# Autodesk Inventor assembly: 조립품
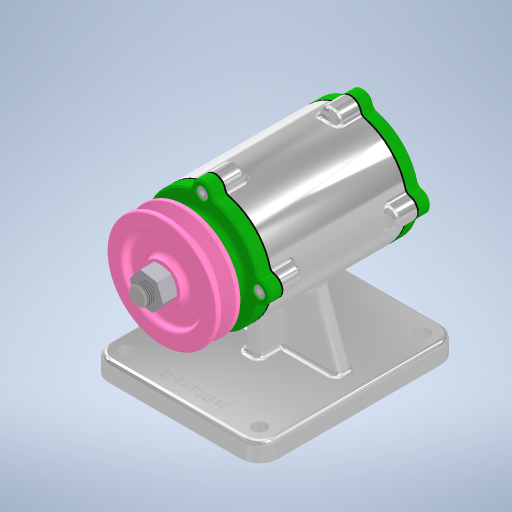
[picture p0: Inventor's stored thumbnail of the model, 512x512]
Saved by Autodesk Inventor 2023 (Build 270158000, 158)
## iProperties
Created: 2023-08
Part Number: 조립품
Document SubType Name: Assembly
Designer: asung
Author: asung
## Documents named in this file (12)
- C:\Users\asung\Desktop\730808V1003\조립품.iam
- C:\Users\asung\Desktop\730808V1003\본체.ipt
- C:\Users\asung\Desktop\730808V1003\730808V1003\앞커버.ipt
- C:\Users\asung\Desktop\730808V1003\730808V1003\개스킷.ipt
- C:\Users\asung\Desktop\730808V1003\730808V1003\뒤커버.ipt
- C:\Users\asung\Desktop\730808V1003\730808V1003\축.ipt
- C:\Users\asung\Desktop\730808V1003\730808V1003\베어링 6204.ipt
- C:\Users\asung\Desktop\730808V1003\730808V1003\볼트 M4 x 12.ipt
- C:\Users\asung\Desktop\730808V1003\730808V1003\키 4 x 4.ipt
- C:\Users\asung\Desktop\730808V1003\730808V1003\오일 실.ipt
- C:\Users\asung\Desktop\730808V1003\730808V1003\V-벨트풀리.ipt
- C:\Users\asung\Desktop\730808V1003\730808V1003\너트 M12 x 1.25.ipt
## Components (8 placed, 6 different names)
1. 개스킷:1
2. 개스킷:2
3. KS B 2023 6204 - 20 x 47 x 14:1
4. KS B 2023 6204 - 20 x 47 x 14:2
5. KS B 1311 (I) 4 x 4 x 12:1
6. KS B 2804 D D - 20 32 8:1
7. V-벨트풀리:1
8. KS B 1012 클래스 1 일반 - 미터 M12x1.25:1
